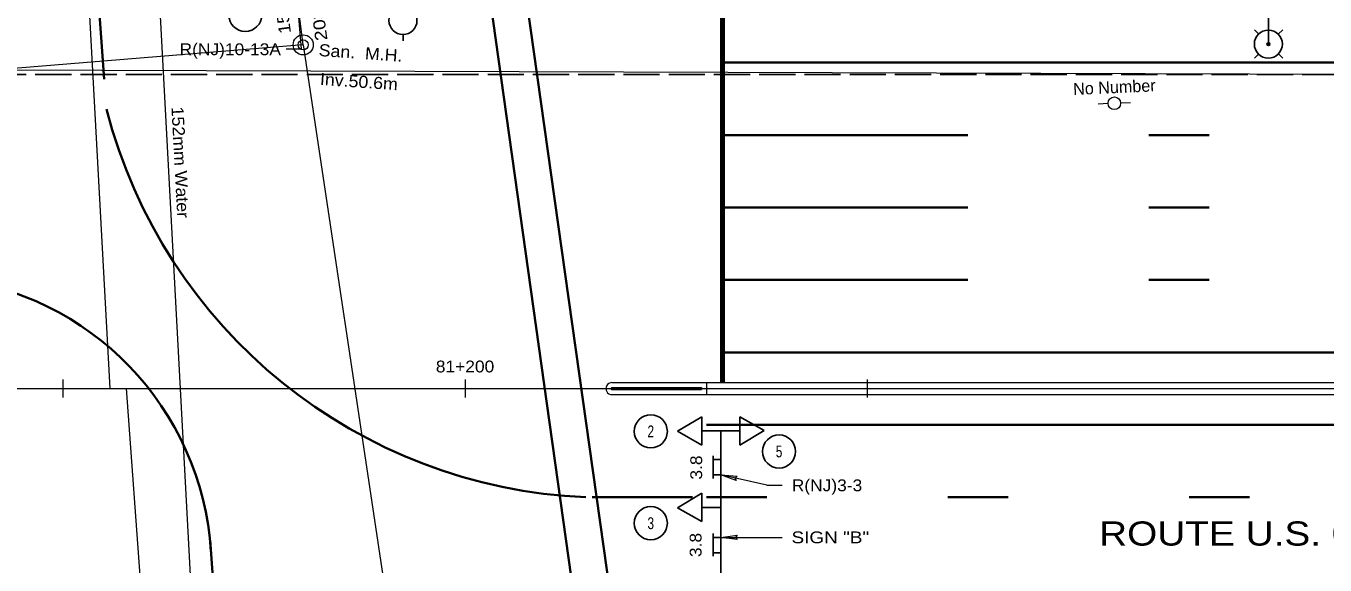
# Model space of a CAD drawing. Extents: x 168203 to 169863, y 223196 to 223870.
# Drawn here: x 168345.6 to 168410.2, y 223625.5 to 223652.3 of the extents above; entities that cross this region are included whole.
import ezdxf
from ezdxf.enums import TextEntityAlignment as Align

# ---------------------------------------------------------------- set-up
doc = ezdxf.new("R2010")
doc.units = 0
doc.header["$LTSCALE"] = 0.3
doc.header["$PDMODE"] = 32
doc.header["$PDSIZE"] = 0.15
doc.linetypes.add('LONG_DASH_SHORT_DASH', pattern=[9.9, 6, -1.2, 1.5, -1.2])
doc.linetypes.add('LONG_DASHED', pattern=[7.5, 6, -1.5])
for name, color, linetype, lineweight in [('1', 7, 'Continuous', 13), ('23', 7, 'Continuous', 25), ('31', 7, 'Continuous', 25), ('36', 7, 'Continuous', 35), ('5', 7, 'Continuous', 25), ('7', 7, 'Continuous', 25)]:
    doc.layers.add(name, color=color, linetype=linetype, lineweight=lineweight)

msp = doc.modelspace()

# ---------------------------------------------------------------- linework, layer by layer
at = {"layer": '1'}
for p, q in [((168349.7975, 223634.2675), (168346.0287, 223703.2124)), ((168347.4514, 223634.7175), (168347.4514, 223633.8175)), ((168367.4514, 223634.7175), (168367.4514, 223633.8175)), ((168374.7516, 223634.5668), (168379.4515, 223634.5676)), ((168374.7517, 223634.3168), (168379.2017, 223634.3176)), ((168379.2017, 223634.3176), (168379.2017, 223634.2175)), ((168379.4515, 223634.5676), (168379.4516, 223633.9676)), ((168379.4515, 223634.5676), (168427.4519, 223634.5676)), ((168387.4514, 223634.7175), (168387.4514, 223633.8175)), ((168298.0344, 223634.2675), (168427.4519, 223634.2676)), ((168355.9956, 223559.8648), (168350.6186, 223634.2675)), ((168374.7517, 223634.2167), (168379.2017, 223634.2175)), ((168374.7517, 223633.9668), (168379.4515, 223633.9676)), ((168379.4515, 223633.9676), (168427.4519, 223633.9677))]:
    msp.add_line(p, q, dxfattribs=at)
for radius in [0.3, 0.05]:
    msp.add_arc((168374.7516, 223634.2668), radius, 90, 270.0191, dxfattribs=at)
at = {"layer": '23', "lineweight": 13}
for p, q in [((168357.586, 223554.132), (168349.5897, 223703.4835)), ((168359.4003, 223651.3453), (168352.7333, 223703.4586)), ((168359.4003, 223651.3453), (168318.5983, 223648.0208)), ((168359.4003, 223651.3453), (168367.4305, 223597.8004)), ((168317.2096, 223650.1818), (168433.5316, 223649.8335)), ((168399.4232, 223648.4312), (168398.9238, 223648.4085)), ((168400.0476, 223648.4596), (168400.5471, 223648.4823))]:
    msp.add_line(p, q, dxfattribs=at)
for centre, radius in [((168359.4003, 223651.3453), 0.5), ((168359.4003, 223651.3453), 0.25), ((168399.7354, 223648.4454), 0.3125)]:
    msp.add_circle(centre, radius, dxfattribs=at)
at = {"layer": '31'}
for p, q in [((168407.4002, 223655.9857), (168407.4002, 223651.3857)), ((168380.1659, 223632.1676), (168379.2261, 223632.1676)), ((168380.1659, 223613.8676), (168380.1659, 223632.1676)), ((168380.1659, 223632.1676), (168381.1057, 223632.1676)), ((168379.7863, 223630.9339), (168379.7863, 223629.8044)), ((168379.7863, 223630.7441), (168380.1658, 223630.7441)), ((168379.7863, 223629.9851), (168380.1658, 223629.9851)), ((168380.1659, 223628.3676), (168379.2261, 223628.3676)), ((168379.7864, 223627.0626), (168379.7864, 223625.9331)), ((168379.7864, 223626.8728), (168380.1659, 223626.8728)), ((168379.7864, 223626.1138), (168380.1659, 223626.1138))]:
    msp.add_line(p, q, dxfattribs=at)
at = {"layer": '31', "lineweight": 13}
for p, q in [((168382.4555, 223629.4678), (168380.1658, 223629.9851)), ((168382.4555, 223629.4678), (168383.2142, 223629.4678)), ((168380.1659, 223626.8728), (168383.2142, 223626.8728))]:
    msp.add_line(p, q, dxfattribs=at)
msp.add_lwpolyline([(168358.5538, 223651.1547), (168359.3125, 223651.1547), (168358.8755, 223656.4839)], dxfattribs=at)
at = {"layer": '31', "linetype": 'LONG_DASH_SHORT_DASH'}
for points in [[(168378.0063, 223632.1495), (168379.2261, 223631.4628), (168379.2261, 223632.1676), (168379.2261, 223632.8724)], [(168382.3255, 223632.1857), (168381.1057, 223632.8724), (168381.1057, 223632.1676), (168381.1057, 223631.4628)], [(168378.0063, 223628.3495), (168379.2261, 223627.6628), (168379.2261, 223628.3676), (168379.2261, 223629.0724)]]:
    msp.add_lwpolyline(points, close=True, dxfattribs=at)
at = {"layer": '31', "lineweight": 13}
for points in [[(168380.9372, 223629.7089), (168380.1658, 223629.9851), (168380.983, 223629.9116), (168380.8797, 223629.8238)], [(168380.9792, 223626.7734), (168380.1659, 223626.8728), (168380.9792, 223626.9812), (168380.8978, 223626.8728)]]:
    msp.add_lwpolyline(points, close=True, dxfattribs=at)
at = {"layer": '31'}
for centre in [(168356.52, 223652.8356), (168376.6839, 223632.1434), (168383.0633, 223631.1445), (168376.6839, 223627.579)]:
    msp.add_circle(centre, 0.8236, dxfattribs=at)
at = {"layer": '36'}
for p, q in [((168349.5082, 223649.6433), (168348.9759, 223657.0092)), ((168374.0279, 223615.7265), (168368.7066, 223653.4676)), ((168375.8367, 223615.7899), (168370.5243, 223653.4676)), ((168380.2468, 223650.4671), (168431.5307, 223650.4672)), ((168380.2468, 223646.8671), (168392.4521, 223646.8671)), ((168401.4521, 223646.8671), (168404.4521, 223646.8671)), ((168380.2469, 223643.2671), (168392.452, 223643.2672)), ((168401.4521, 223643.2672), (168404.4521, 223643.2672)), ((168380.2469, 223639.6672), (168392.4521, 223639.6672)), ((168401.4521, 223639.6672), (168404.4521, 223639.6672)), ((168380.2469, 223636.0672), (168427.4519, 223636.0672)), ((168379.4521, 223632.4672), (168427.4519, 223632.4672)), ((168373.7721, 223628.8671), (168378.7516, 223628.8671)), ((168379.4522, 223628.8671), (168382.4522, 223628.8671)), ((168391.4522, 223628.8671), (168394.4522, 223628.8671)), ((168403.4522, 223628.8671), (168406.4522, 223628.8671)), ((168355.7208, 223613.6203), (168354.7732, 223626.7317))]:
    msp.add_line(p, q, dxfattribs=at)
at = {"layer": '36', "lineweight": 80}
msp.add_line((168380.2469, 223634.5676), (168380.2468, 223653.4676), dxfattribs=at)
at = {"layer": '36'}
for centre, radius, start, end in [((168374.5533, 223654.6027), 25.759, 194.51362, 267.55708), ((168340.2591, 223625.2498), 14.5836, 3.68649, 84.22505)]:
    msp.add_arc(centre, radius, start, end, dxfattribs=at)
at = {"layer": '5', "linetype": 'LONG_DASHED'}
msp.add_line((168332.5747, 223649.8768), (168431.2156, 223649.8769), dxfattribs=at)
at = {"layer": '7'}
for p, q in [((168364.3776, 223651.8642), (168364.3712, 223651.551)), ((168406.7044, 223652.0905), (168406.9122, 223651.8917)), ((168408.1141, 223652.0996), (168407.8882, 223651.8737)), ((168406.9032, 223650.8887), (168406.7044, 223650.6809)), ((168407.8972, 223650.9068), (168408.1141, 223650.6809))]:
    msp.add_line(p, q, dxfattribs=at)
for centre in [(168364.3616, 223652.5574), (168407.3957, 223651.3857)]:
    msp.add_circle(centre, 0.6965, dxfattribs=at)
msp.add_point((168407.4002, 223651.3857), dxfattribs=at)

# ---------------------------------------------------------------- texts
at = {"layer": '1'}
for s, height, width, p in [('81+200', 0.5873, 1.1, (168367.4477, 223635.0724)), ('ROUTE U.S. 00', 1.202, 1.2, (168405.8363, 223626.4662))]:
    msp.add_text(s, height=height, dxfattribs=dict(at, width=width)).set_placement(p, align=Align.CENTER)
at = {"layer": '23'}
for s, rotation, width, p in [('152mm Force & ', 97.692, 1.15, (168358.3408, 223655.3191)), ('203mm Sanitary', 97.692, 1.2, (168360.1428, 223655.0662)), ('San.  M.H.', 356.065, 1.1, (168362.2352, 223650.6533)), ('Inv.50.6m', 356.065, 1.1, (168362.1529, 223649.2238)), ('152mm Water', 273.065, 1.1, (168352.9947, 223645.4967))]:
    msp.add_text(s, height=0.6, rotation=rotation, dxfattribs=dict(at, width=width)).set_placement(p, align=Align.CENTER)
msp.add_text('No Number', height=0.6, rotation=2.6, dxfattribs=at).set_placement((168399.75, 223648.9465), align=Align.CENTER)
at = {"layer": '31'}
for s, width, p in [('R(NJ)10-13A', 1.1, (168355.7725, 223650.8348)), ('2', 0.75, (168376.684, 223631.8498)), ('5', 0.75, (168383.0634, 223630.8509)), ('R(NJ)3-3', 1.1, (168385.448, 223629.1678)), ('3', 0.75, (168376.684, 223627.2854)), ('SIGN "B"', 1.2, (168385.6128, 223626.5829))]:
    msp.add_text(s, height=0.5873, dxfattribs=dict(at, width=width)).set_placement(p, align=Align.CENTER)
at = {"layer": '31', "width": 1.1}
for p in [(168379.2374, 223630.3457), (168379.2067, 223626.4965)]:
    msp.add_text('3.8', height=0.5873, rotation=90, dxfattribs=at).set_placement(p, align=Align.CENTER)

doc.saveas('drawing.dxf')
